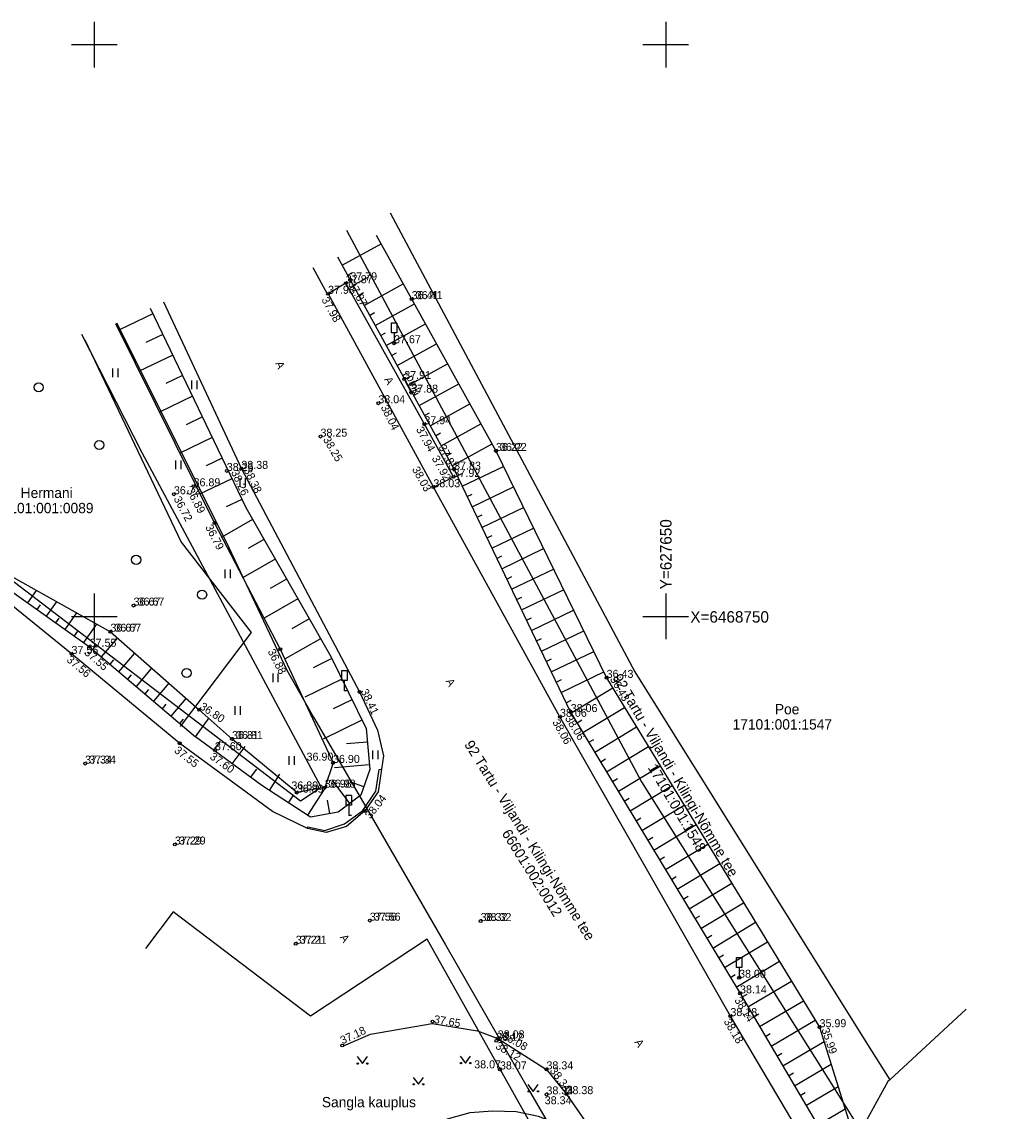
# Model space of a CAD drawing. Extents: x 627548 to 628052, y 6467984 to 6468802.
# Drawn here: x 627593.7 to 627678.5, y 6468706.7 to 6468802 of the extents above; entities that cross this region are included whole.
import ezdxf

# ---------------------------------------------------------------- set-up
doc = ezdxf.new("R2010")
doc.units = 0
for name, color, linetype in [('HALJASTUS', 7, 'Continuous'), ('KORGUS-EH2000', 7, 'Continuous'), ('LIIKLUS', 7, 'Continuous'), ('MOOTKORG-EH2000', 7, 'Continuous'), ('MOOTMPUNKT', 7, 'Continuous'), ('PIIR', 7, 'Continuous'), ('RAJATIS', 7, 'Continuous'), ('RELJEEF', 7, 'Continuous'), ('SITRASS', 7, 'Continuous'), ('TEE', 7, 'Continuous'), ('VORK', 7, 'Continuous')]:
    doc.layers.add(name, color=color, linetype=linetype)

msp = doc.modelspace()

# ---------------------------------------------------------------- linework, layer by layer
at = {"layer": 'HALJASTUS'}
for p, q in [((627601.604, 6468771.681), (627601.604, 6468770.92)), ((627602.059, 6468771.681), (627602.059, 6468770.92)), ((627608.508, 6468770.618), (627608.508, 6468769.857)), ((627608.963, 6468770.618), (627608.963, 6468769.857)), ((627607.114, 6468763.632), (627607.114, 6468762.871)), ((627607.569, 6468763.632), (627607.569, 6468762.871)), ((627612.747, 6468762.09), (627612.747, 6468761.328)), ((627613.202, 6468762.09), (627613.202, 6468761.328)), ((627611.418, 6468754.106), (627611.418, 6468753.344)), ((627611.873, 6468754.106), (627611.873, 6468753.344)), ((627615.616, 6468745.008), (627615.616, 6468744.246)), ((627616.071, 6468745.008), (627616.071, 6468744.246)), ((627612.309, 6468742.143), (627612.309, 6468741.382)), ((627612.764, 6468742.143), (627612.764, 6468741.382)), ((627617.026, 6468737.78), (627617.026, 6468737.019)), ((627617.481, 6468737.78), (627617.481, 6468737.019)), ((627624.349, 6468738.257), (627624.349, 6468737.496)), ((627624.804, 6468738.257), (627624.804, 6468737.496)), ((627622.988, 6468711.493), (627623.452, 6468710.886)), ((627623.452, 6468710.886), (627623.897, 6468711.493)), ((627632.011, 6468711.536), (627632.475, 6468710.929)), ((627632.475, 6468710.929), (627632.92, 6468711.536)), ((627627.889, 6468709.682), (627628.352, 6468709.075)), ((627628.352, 6468709.075), (627628.798, 6468709.682)), ((627637.933, 6468709.066), (627638.397, 6468708.459)), ((627638.397, 6468708.459), (627638.842, 6468709.066))]:
    msp.add_line(p, q, dxfattribs=at)
msp.add_lwpolyline([(627599.184, 6468774.197), (627607.615, 6468756.497), (627613.733, 6468748.584), (627607.526, 6468740.359)], dxfattribs=at)
for centre, radius in [((627595.138, 6468770.029), 0.4), ((627600.432, 6468764.979), 0.4), ((627603.662, 6468754.941), 0.4), ((627609.433, 6468751.89), 0.4), ((627608.072, 6468745.043), 0.4), ((627623.05, 6468710.886), 0.055), ((627623.879, 6468710.886), 0.055), ((627632.074, 6468710.929), 0.055), ((627632.902, 6468710.929), 0.055), ((627627.951, 6468709.075), 0.055), ((627628.78, 6468709.075), 0.055), ((627637.996, 6468708.459), 0.055), ((627638.824, 6468708.459), 0.055)]:
    msp.add_circle(centre, radius, dxfattribs=at)
at = {"layer": 'KORGUS-EH2000'}
for centre in [(627610.53, 6468758.157), (627616.27, 6468747.137), (627623.2, 6468743.387), (627609.17, 6468741.837), (627607.47, 6468738.897), (627623.66, 6468732.977), (627629.59, 6468714.557), (627621.7, 6468712.467)]:
    msp.add_circle(centre, 0.125, dxfattribs=at)
at = {"layer": 'LIIKLUS'}
for points in [[(627625.979, 6468775.636), (627625.979, 6468774.786)], [(627626.479, 6468775.636), (627625.979, 6468775.636)], [(627626.479, 6468775.636), (627626.479, 6468774.786)], [(627626.479, 6468774.786), (627625.979, 6468774.786)], [(627626.229, 6468774.786), (627626.229, 6468773.886)], [(627626.479, 6468773.886), (627626.229, 6468773.886)], [(627621.621, 6468745.236), (627621.621, 6468744.386)], [(627622.121, 6468745.236), (627621.621, 6468745.236)], [(627622.121, 6468744.386), (627621.621, 6468744.386)], [(627621.871, 6468744.386), (627621.871, 6468743.486)], [(627622.121, 6468745.236), (627622.121, 6468744.386)], [(627622.121, 6468743.486), (627621.871, 6468743.486)], [(627622.007, 6468734.343), (627622.007, 6468733.493)], [(627622.507, 6468734.343), (627622.007, 6468734.343)], [(627622.507, 6468734.343), (627622.507, 6468733.493)], [(627622.507, 6468733.493), (627622.007, 6468733.493)], [(627622.257, 6468733.493), (627622.257, 6468732.593)], [(627622.507, 6468732.593), (627622.257, 6468732.593)], [(627656.162, 6468720.145), (627656.162, 6468719.295)], [(627656.662, 6468720.145), (627656.162, 6468720.145)], [(627656.662, 6468720.145), (627656.662, 6468719.295)], [(627656.662, 6468719.295), (627656.162, 6468719.295)], [(627656.412, 6468719.295), (627656.412, 6468718.395)], [(627656.662, 6468718.395), (627656.412, 6468718.395)]]:
    msp.add_lwpolyline(points, dxfattribs=at)
at = {"layer": 'MOOTMPUNKT'}
for centre in [(627622.01, 6468779.136), (627622.401, 6468779.39), (627620.451, 6468778.209), (627627.773, 6468777.744), (627626.229, 6468773.886), (627627.12, 6468770.758), (627627.735, 6468769.565), (627624.852, 6468768.638), (627628.878, 6468766.802), (627619.79, 6468765.718), (627635.143, 6468764.467), (627611.59, 6468762.718), (627612.866, 6468762.898), (627631.48, 6468762.833), (627631.43, 6468762.199), (627606.965, 6468760.68), (627608.685, 6468761.377), (627629.668, 6468761.293), (627603.438, 6468750.942), (627601.41, 6468748.658), (627599.591, 6468747.343), (627598.002, 6468746.714), (627644.826, 6468744.62), (627641.678, 6468741.628), (627640.744, 6468741.218), (627612.048, 6468739.271), (627610.555, 6468738.292), (627599.196, 6468737.124), (627620.886, 6468737.184), (627620.169, 6468735.021), (627617.712, 6468734.584), (627607.052, 6468730.045), (627624.109, 6468723.387), (627633.799, 6468723.353), (627617.624, 6468721.368), (627656.412, 6468718.395), (627656.496, 6468717.027), (627655.655, 6468715.038), (627663.453, 6468714.069), (627635.182, 6468712.878), (627635.3, 6468713.094), (627635.489, 6468710.375), (627639.562, 6468710.382), (627639.56, 6468708.189), (627641.314, 6468708.212)]:
    msp.add_circle(centre, 0.125, dxfattribs=at)
at = {"layer": 'PIIR'}
for p, q in [((627625.884, 6468785.292), (627647.29, 6468745.15)), ((627622.064, 6468783.785), (627647.89, 6468735.54)), ((627604.18, 6468764.29), (627598.902, 6468774.65)), ((627619.84, 6468735.06), (627604.18, 6468764.29)), ((627588.77, 6468756.22), (627618.05, 6468733.86)), ((627647.29, 6468745.15), (627667.66, 6468712.55)), ((627618.05, 6468733.86), (627619.84, 6468735.06)), ((627647.89, 6468735.54), (627664.81, 6468708.59)), ((627606.91, 6468724.16), (627604.484, 6468720.962)), ((627618.92, 6468715.04), (627606.91, 6468724.16)), ((627629.12, 6468721.76), (627618.92, 6468715.04)), ((627646.31, 6468691.19), (627629.12, 6468721.76)), ((627669.59, 6468709.46), (627676.272, 6468715.659)), ((627667.66, 6468712.55), (627669.59, 6468709.46)), ((627669.44, 6468709.31), (627667.19, 6468705.25)), ((627669.59, 6468709.46), (627669.44, 6468709.31)), ((627664.81, 6468708.59), (627667, 6468705.1))]:
    msp.add_line(p, q, dxfattribs=at)
at = {"layer": 'RAJATIS'}
msp.add_lwpolyline([(627627.12, 6468770.758), (627627.735, 6468769.565)], dxfattribs=at)
at = {"layer": 'RELJEEF'}
for p, q in [((627621.68, 6468780.705), (627625.109, 6468782.586)), ((627622.167, 6468779.832), (627622.605, 6468780.072)), ((627622.641, 6468778.952), (627623.957, 6468779.673)), ((627623.603, 6468777.198), (627627.032, 6468779.078)), ((627623.122, 6468778.075), (627623.561, 6468778.315)), ((627624.565, 6468775.444), (627628.003, 6468777.33)), ((627605.131, 6468776.464), (627602.198, 6468775.058)), ((627624.084, 6468776.321), (627624.522, 6468776.562)), ((627625.526, 6468773.691), (627628.974, 6468775.581)), ((627605.995, 6468774.661), (627604.516, 6468773.952)), ((627625.045, 6468774.567), (627625.484, 6468774.808)), ((627626.007, 6468772.814), (627626.445, 6468773.054)), ((627626.488, 6468771.937), (627629.944, 6468773.832)), ((627606.86, 6468772.857), (627603.927, 6468771.452)), ((627627.449, 6468770.183), (627630.915, 6468772.084)), ((627607.724, 6468771.054), (627606.27, 6468770.357)), ((627626.969, 6468771.06), (627627.407, 6468771.301)), ((627628.411, 6468768.43), (627631.886, 6468770.335)), ((627608.589, 6468769.25), (627605.706, 6468767.868)), ((627627.93, 6468769.306), (627628.369, 6468769.547)), ((627629.373, 6468766.676), (627632.856, 6468768.586)), ((627609.454, 6468767.447), (627608.024, 6468766.762)), ((627628.892, 6468767.553), (627629.33, 6468767.793)), ((627630.334, 6468764.922), (627633.827, 6468766.838)), ((627610.318, 6468765.644), (627607.484, 6468764.285)), ((627629.853, 6468765.799), (627630.292, 6468766.04)), ((627631.296, 6468763.169), (627634.798, 6468765.089)), ((627611.183, 6468763.84), (627609.778, 6468763.167)), ((627630.815, 6468764.046), (627631.254, 6468764.286)), ((627631.747, 6468762.277), (627632.198, 6468762.494)), ((627632.181, 6468761.376), (627635.802, 6468763.117)), ((627612.047, 6468762.037), (627609.263, 6468760.702)), ((627632.614, 6468760.474), (627633.065, 6468760.691)), ((627633.048, 6468759.573), (627636.679, 6468761.319)), ((627612.912, 6468760.233), (627611.532, 6468759.572)), ((627633.481, 6468758.672), (627633.932, 6468758.889)), ((627633.915, 6468757.771), (627637.556, 6468759.522)), ((627613.852, 6468758.469), (627611.163, 6468756.936)), ((627634.781, 6468755.968), (627638.433, 6468757.724)), ((627634.348, 6468756.87), (627634.799, 6468757.086)), ((627614.842, 6468756.732), (627613.465, 6468755.946)), ((627635.648, 6468754.166), (627639.31, 6468755.927)), ((627615.833, 6468754.994), (627613.012, 6468753.386)), ((627635.215, 6468755.067), (627635.665, 6468755.284)), ((627636.515, 6468752.364), (627640.187, 6468754.129)), ((627616.824, 6468753.257), (627615.381, 6468752.434)), ((627636.082, 6468753.265), (627636.532, 6468753.482)), ((627594.18, 6468751.175), (627594.949, 6468752.261)), ((627637.382, 6468750.561), (627641.064, 6468752.332)), ((627595.812, 6468750.019), (627596.679, 6468751.243)), ((627617.815, 6468751.52), (627614.862, 6468749.836)), ((627636.948, 6468751.462), (627637.399, 6468751.679)), ((627594.996, 6468750.597), (627595.285, 6468751.005)), ((627597.444, 6468748.863), (627598.463, 6468750.302)), ((627638.249, 6468748.759), (627641.94, 6468750.534)), ((627596.628, 6468749.441), (627596.917, 6468749.849)), ((627599.076, 6468747.707), (627600.219, 6468749.322)), ((627618.806, 6468749.782), (627617.296, 6468748.922)), ((627637.815, 6468749.66), (627638.266, 6468749.877)), ((627598.26, 6468748.285), (627598.549, 6468748.693)), ((627639.115, 6468746.956), (627642.817, 6468748.737)), ((627599.873, 6468747.104), (627600.196, 6468747.485)), ((627600.635, 6468746.457), (627602.036, 6468748.107)), ((627619.796, 6468748.045), (627616.705, 6468746.282)), ((627638.682, 6468747.858), (627639.133, 6468748.074)), ((627602.159, 6468745.162), (627603.539, 6468746.786)), ((627620.776, 6468746.302), (627619.144, 6468745.501)), ((627639.982, 6468745.154), (627643.694, 6468746.939)), ((627601.397, 6468745.809), (627601.721, 6468746.19)), ((627603.684, 6468743.867), (627605.041, 6468745.466)), ((627639.549, 6468746.055), (627639.999, 6468746.272)), ((627602.921, 6468744.515), (627603.245, 6468744.896)), ((627621.657, 6468744.506), (627618.423, 6468742.92)), ((627640.416, 6468744.253), (627640.866, 6468744.47)), ((627640.849, 6468743.352), (627644.571, 6468745.142)), ((627604.446, 6468743.22), (627604.77, 6468743.601)), ((627605.208, 6468742.573), (627606.543, 6468744.145)), ((627641.723, 6468741.553), (627645.36, 6468743.744)), ((627606.733, 6468741.278), (627608.045, 6468742.824)), ((627622.537, 6468742.711), (627620.913, 6468741.913)), ((627641.282, 6468742.45), (627641.733, 6468742.667)), ((627605.97, 6468741.925), (627606.294, 6468742.307)), ((627642.755, 6468739.84), (627646.401, 6468742.036)), ((627607.495, 6468740.631), (627607.819, 6468741.012)), ((627608.852, 6468739.478), (627610.064, 6468741.12)), ((627623.418, 6468740.915), (627620.027, 6468739.251)), ((627642.239, 6468740.697), (627642.667, 6468740.955)), ((627643.787, 6468738.127), (627647.442, 6468740.329)), ((627610.461, 6468738.29), (627611.044, 6468739.08)), ((627623.882, 6468739.003), (627622.068, 6468738.84)), ((627643.271, 6468738.983), (627643.699, 6468739.241)), ((627612.07, 6468737.102), (627613.19, 6468738.619)), ((627644.819, 6468736.414), (627648.484, 6468738.621)), ((627624.06, 6468737.011), (627621.022, 6468736.739)), ((627644.303, 6468737.27), (627644.731, 6468737.528)), ((627645.851, 6468734.7), (627649.525, 6468736.913)), ((627613.679, 6468735.914), (627614.215, 6468736.641)), ((627615.316, 6468734.767), (627616.23, 6468736.186)), ((627645.335, 6468735.557), (627645.763, 6468735.815)), ((627618.678, 6468732.6), (627620.37, 6468735.225)), ((627622.344, 6468733.634), (627620.894, 6468735.591)), ((627623.576, 6468735.1), (627622.445, 6468735.492)), ((627646.883, 6468732.987), (627650.566, 6468735.206)), ((627616.997, 6468733.684), (627617.446, 6468734.381)), ((627620.606, 6468732.748), (627620.395, 6468733.922)), ((627646.367, 6468733.844), (627646.795, 6468734.102)), ((627647.915, 6468731.274), (627651.607, 6468733.498)), ((627647.399, 6468732.13), (627647.827, 6468732.388)), ((627648.947, 6468729.561), (627652.648, 6468731.79)), ((627648.431, 6468730.417), (627648.859, 6468730.675)), ((627649.978, 6468727.847), (627653.689, 6468730.083)), ((627649.463, 6468728.704), (627649.891, 6468728.962)), ((627651.01, 6468726.134), (627654.731, 6468728.375)), ((627650.494, 6468726.991), (627650.923, 6468727.249)), ((627652.042, 6468724.421), (627655.772, 6468726.667)), ((627651.526, 6468725.278), (627651.955, 6468725.536)), ((627653.074, 6468722.708), (627656.813, 6468724.96)), ((627652.558, 6468723.564), (627652.987, 6468723.822)), ((627654.106, 6468720.995), (627657.854, 6468723.252)), ((627653.59, 6468721.851), (627654.019, 6468722.109)), ((627655.138, 6468719.281), (627658.895, 6468721.544)), ((627654.622, 6468720.138), (627655.05, 6468720.396)), ((627656.17, 6468717.568), (627659.936, 6468719.837)), ((627655.654, 6468718.425), (627656.082, 6468718.683)), ((627657.19, 6468715.848), (627661.001, 6468718.091)), ((627656.683, 6468716.71), (627657.114, 6468716.963)), ((627658.205, 6468714.124), (627662.042, 6468716.383)), ((627657.698, 6468714.986), (627658.128, 6468715.24)), ((627659.22, 6468712.401), (627663.083, 6468714.676)), ((627658.712, 6468713.263), (627659.143, 6468713.516)), ((627660.234, 6468710.677), (627663.849, 6468712.805)), ((627659.727, 6468711.539), (627660.158, 6468711.793)), ((627661.249, 6468708.954), (627664.462, 6468710.846)), ((627660.742, 6468709.816), (627661.173, 6468710.069)), ((627661.756, 6468708.092), (627662.187, 6468708.346)), ((627662.264, 6468707.231), (627665.076, 6468708.886)), ((627663.279, 6468705.507), (627665.69, 6468706.927))]:
    msp.add_line(p, q, dxfattribs=at)
for points in [[(627624.669, 6468783.336), (627635.143, 6468764.467), (627644.826, 6468744.62), (627663.453, 6468714.069), (627667.771, 6468700.282), (627669.788, 6468697.789), (627680.393, 6468682.345), (627695.175, 6468659.082), (627697.462, 6468659.655)], [(627621.271, 6468781.45), (627631.48, 6468762.833), (627641.678, 6468741.628), (627656.496, 6468717.027), (627668.985, 6468695.815), (627678.436, 6468681.433), (627690.541, 6468663.778), (627694.507, 6468657.515), (627696.664, 6468657.822), (627698.617, 6468658.584)], [(627604.893, 6468776.962), (627613.259, 6468759.508), (627620.682, 6468746.492), (627623.776, 6468740.186), (627624.097, 6468736.603), (627623.317, 6468734.354), (627621.324, 6468732.877), (627618.919, 6468732.445), (627614.649, 6468735.197), (627608.852, 6468739.478)], [(627601.856, 6468775.622), (627610.525, 6468758.159), (627616.269, 6468747.135), (627620.886, 6468737.184), (627620.169, 6468735.021), (627617.712, 6468734.584), (627612.048, 6468739.271), (627609.172, 6468741.833)], [(627581.804, 6468748.589), (627586.557, 6468753.877), (627589.097, 6468755.524), (627601.41, 6468748.658), (627609.172, 6468741.833)], [(627583.171, 6468747.092), (627588.98, 6468753.47), (627591.233, 6468753.261), (627599.591, 6468747.343), (627608.852, 6468739.478)]]:
    msp.add_lwpolyline(points, dxfattribs=at)
at = {"layer": 'SITRASS'}
msp.add_lwpolyline([(627601.95, 6468775.665), (627611.516, 6468756.586), (627616.834, 6468745.298), (627619.184, 6468741.186), (627623.567, 6468733.678), (627630.719, 6468721.267), (627637.953, 6468708.68), (627647.64, 6468692.032), (627654.507, 6468680.481), (627661.905, 6468667.643), (627667.084, 6468659.838), (627674.129, 6468649.944), (627689.767, 6468629.543), (627695.628, 6468619.665), (627699.564, 6468614.681), (627710.374, 6468599.048), (627720.659, 6468583.91), (627729.18, 6468571.423), (627736.574, 6468559.697), (627746.582, 6468544.707), (627757.269, 6468529.067), (627768.1, 6468513.354)], dxfattribs=at)
at = {"layer": 'TEE'}
for points in [[(627620.411, 6468778.185), (627619.149, 6468780.47)], [(627628.878, 6468766.802), (627622.01, 6468779.136), (627620.451, 6468778.209), (627629.668, 6468761.293), (627631.43, 6468762.199), (627628.878, 6468766.802)], [(627606.044, 6468777.5), (627612.866, 6468762.898), (627623.199, 6468743.388), (627624.786, 6468740.054), (627625.313, 6468737.797), (627625.122, 6468736.644), (627624.836, 6468734.648), (627623.66, 6468732.979), (627622.052, 6468731.609), (627620.296, 6468731.095), (627618.662, 6468731.443), (627615.578, 6468732.934), (627607.474, 6468738.895)], [(627700.939, 6468658.86), (627696.392, 6468656.072), (627693.013, 6468655.978), (627687.872, 6468663.274), (627673.734, 6468684.205), (627667.271, 6468695.423), (627655.655, 6468715.038), (627640.744, 6468741.218), (627629.668, 6468761.293)], [(627607.474, 6468738.895), (627598.002, 6468746.714), (627590.833, 6468752.532), (627589.261, 6468751.587), (627584.254, 6468746.308)], [(627618.662, 6468731.443), (627618.678, 6468731.589), (627620.171, 6468731.286), (627621.894, 6468731.856), (627623.491, 6468733.031), (627624.623, 6468734.719), (627624.934, 6468736.621), (627625.122, 6468736.644)], [(627621.813, 6468712.448), (627624.169, 6468713.467), (627629.552, 6468714.398), (627633.52, 6468713.753), (627635.3, 6468713.094), (627639.562, 6468710.382), (627641.314, 6468708.212), (627643.266, 6468705.375), (627644.837, 6468702.56), (627643.625, 6468703.365), (627640.773, 6468705.527), (627638.868, 6468706.251), (627636.924, 6468706.658), (627634.856, 6468706.73), (627632.859, 6468706.587), (627630.866, 6468706.032), (627629.956, 6468705.539)]]:
    msp.add_lwpolyline(points, dxfattribs=at)
at = {"layer": 'VORK'}
for p, q in [((627600, 6468802), (627600, 6468798)), ((627650, 6468802), (627650, 6468798)), ((627598, 6468800), (627602, 6468800)), ((627648, 6468800), (627652, 6468800)), ((627600, 6468752), (627600, 6468748)), ((627650, 6468752), (627650, 6468748)), ((627598, 6468750), (627602, 6468750)), ((627648, 6468750), (627652, 6468750))]:
    msp.add_line(p, q, dxfattribs=at)

# ---------------------------------------------------------------- texts
at = {"layer": 'KORGUS-EH2000'}
for s, rotation, p in [('37.87', 299.67852, (627622.182, 6468779.071)), ('37.98', 299.27998, (627619.854, 6468777.692)), ('38.04', 296.42721, (627625.046, 6468768.295)), ('37.94', 298.91275, (627628.126, 6468766.363)), ('38.25', 300.44108, (627619.982, 6468765.468)), ('37.83', 297.0142, (627630.097, 6468764.805)), ('37.92', 299.33619, (627629.503, 6468763.825)), ('38.26', 294.57018, (627611.947, 6468762.615)), ('38.38', 295.54062, (627613.058, 6468762.8)), ('38.03', 299.56377, (627627.771, 6468762.863)), ('36.89', 297.71496, (627608.05, 6468760.999)), ('36.72', 297.84717, (627606.924, 6468760.287)), (' 36.79', 297.52154, (627609.568, 6468758.041)), ('37.56', 319.99949, (627597.522, 6468746.106)), ('37.55', 319.00374, (627599.073, 6468746.74)), (' 36.88', 297.06495, (627615.032, 6468747.169)), ('36.43', 300.51738, (627645.089, 6468744.508)), (' 38.41', 295.45467, (627623.181, 6468743.689)), (' 36.80', 326.59541, (627608.944, 6468742.091)), ('38.06', 299.29642, (627640.048, 6468740.764)), ('38.06', 301.68163, (627641.153, 6468741.082)), (' 37.55', 322.45782, (627606.731, 6468738.317)), ('37.60', 323.95932, (627610.043, 6468737.6)), (' 38.04', 51.66121, (627623.996, 6468732.025)), ('38.14', 301.63202, (627655.975, 6468716.439)), (' 37.65', 350.31291, (627629.414, 6468714.49)), (' 37.18', 24.83226, (627621.478, 6468712.452)), ('38.18', 300.73225, (627655.044, 6468714.571)), ('35.99', 288.73879, (627663.605, 6468713.873)), ('38.08', 330.94534, (627635.61, 6468713.121)), ('38.12', 329.49401, (627635.035, 6468712.253)), ('38.34', 306.87086, (627639.813, 6468710.25))]:
    msp.add_text(s, height=0.7, rotation=rotation, dxfattribs=at).set_placement(p)
for s, p in [('36.41', (627628.123, 6468777.744)), ('36.22', (627635.493, 6468764.467)), ('36.67', (627603.788, 6468750.942)), ('36.67', (627601.76, 6468748.658)), ('36.81', (627612.398, 6468739.271)), ('37.34', (627599.546, 6468737.124)), ('36.90', (627618.571, 6468737.379)), ('36.89', (627617.245, 6468734.863)), ('36.98', (627620.519, 6468735.021)), ('37.29', (627607.402, 6468730.045)), ('37.56', (627624.459, 6468723.387)), ('38.32', (627634.149, 6468723.353)), ('37.21', (627617.974, 6468721.368)), ('38.07', (627633.239, 6468710.468)), ('38.34', (627639.409, 6468707.331))]:
    msp.add_text(s, height=0.7, dxfattribs=at).set_placement(p)
at = {"layer": 'MOOTKORG-EH2000'}
for s, p in [('37.87', (627622.01, 6468779.136)), ('37.79', (627622.401, 6468779.39)), ('37.98', (627620.451, 6468778.209)), ('36.41', (627627.773, 6468777.744)), ('37.67', (627626.229, 6468773.886)), ('37.91', (627627.12, 6468770.758)), ('37.88', (627627.735, 6468769.565)), ('38.04', (627624.852, 6468768.638)), ('37.94', (627628.878, 6468766.802)), ('38.25', (627619.79, 6468765.718)), ('36.22', (627635.143, 6468764.467)), ('38.38', (627612.866, 6468762.898)), ('37.83', (627631.48, 6468762.833)), ('38.26', (627611.59, 6468762.718)), ('37.92', (627631.43, 6468762.199)), ('36.89', (627608.685, 6468761.377)), ('38.03', (627629.668, 6468761.293)), ('36.72', (627606.965, 6468760.68)), ('36.67', (627603.438, 6468750.942)), ('36.67', (627601.41, 6468748.658)), ('37.56', (627598.002, 6468746.714)), ('37.55', (627599.591, 6468747.343)), ('36.43', (627644.826, 6468744.62)), ('38.06', (627640.744, 6468741.218)), ('38.06', (627641.678, 6468741.628)), ('36.81', (627612.048, 6468739.271)), ('37.60', (627610.555, 6468738.292)), ('37.34', (627599.196, 6468737.124)), ('36.90', (627620.886, 6468737.184)), ('36.89', (627617.712, 6468734.584)), ('36.98', (627620.169, 6468735.021)), ('37.29', (627607.052, 6468730.045)), ('37.56', (627624.109, 6468723.387)), ('38.32', (627633.799, 6468723.353)), ('37.21', (627617.624, 6468721.368)), ('38.00', (627656.412, 6468718.395)), ('38.14', (627656.496, 6468717.027)), ('38.18', (627655.655, 6468715.038)), ('35.99', (627663.453, 6468714.069)), ('38.12', (627635.182, 6468712.878)), ('38.08', (627635.3, 6468713.094)), ('38.07', (627635.489, 6468710.375)), ('38.34', (627639.562, 6468710.382)), ('38.34', (627639.56, 6468708.189)), ('38.38', (627641.314, 6468708.212))]:
    msp.add_text(s, height=0.7, dxfattribs=at).set_placement(p)
at = {"layer": 'PIIR'}
for s, p in [('Hermani', (627593.56, 6468760.355)), ('17101:001:0089', (627591.23, 6468759.024)), ('Poe', (627659.546, 6468741.433)), ('17101:001:1547', (627655.844, 6468740.102)), ('Sangla kauplus', (627619.912, 6468707.066))]:
    msp.add_text(s, height=0.9, dxfattribs=at).set_placement(p)
for s, rotation, p in [('92 Tartu - Viljandi - Kilingi-Nõmme tee', 300.49242, (627645.311, 6468744.639)), ('92 Tartu - Viljandi - Kilingi-Nõmme tee', 301.9693, (627632.336, 6468738.799)), ('17101:001:1548', 300.49242, (627648.394, 6468736.78)), ('66601:002:0012', 301.9693, (627635.621, 6468731.022))]:
    msp.add_text(s, height=0.9, rotation=rotation, dxfattribs=at).set_placement(p)
at = {"layer": 'RAJATIS'}
msp.add_text('pink', height=0.7, rotation=294.33714, dxfattribs=at).set_placement((627627.286, 6468770.927))
at = {"layer": 'TEE'}
for rotation, p in [(292.7693, (627615.829, 6468772.135)), (298.49083, (627625.339, 6468770.728)), (298.49083, (627630.725, 6468744.335)), (302.18787, (627621.461, 6468721.927)), (302.18787, (627647.238, 6468712.763))]:
    msp.add_text('A', height=0.7, rotation=rotation, dxfattribs=at).set_placement(p)
at = {"layer": 'VORK'}
msp.add_text('Y=627650 ', height=1, rotation=90, dxfattribs=at).set_placement((627650.507, 6468752.361))
msp.add_text('X=6468750 ', height=1, dxfattribs=at).set_placement((627652.146, 6468749.454))

doc.saveas('drawing.dxf')
